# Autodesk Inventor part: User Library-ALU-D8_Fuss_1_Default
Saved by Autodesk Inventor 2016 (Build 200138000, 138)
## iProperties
Created: 2012-01
Part Number: User Library-ALU-D8_Fuss_1_Default
Document SubType Name: Modeling
Designer: Trevor
Density: 1 g/cm^3
Material: Generic
Appearance: 29,29,29
Author: Trevor
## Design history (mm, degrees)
feature "Base1"
node "Imported1"
